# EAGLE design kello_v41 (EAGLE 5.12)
TP_SIGNAL_NAME: IC4SDO
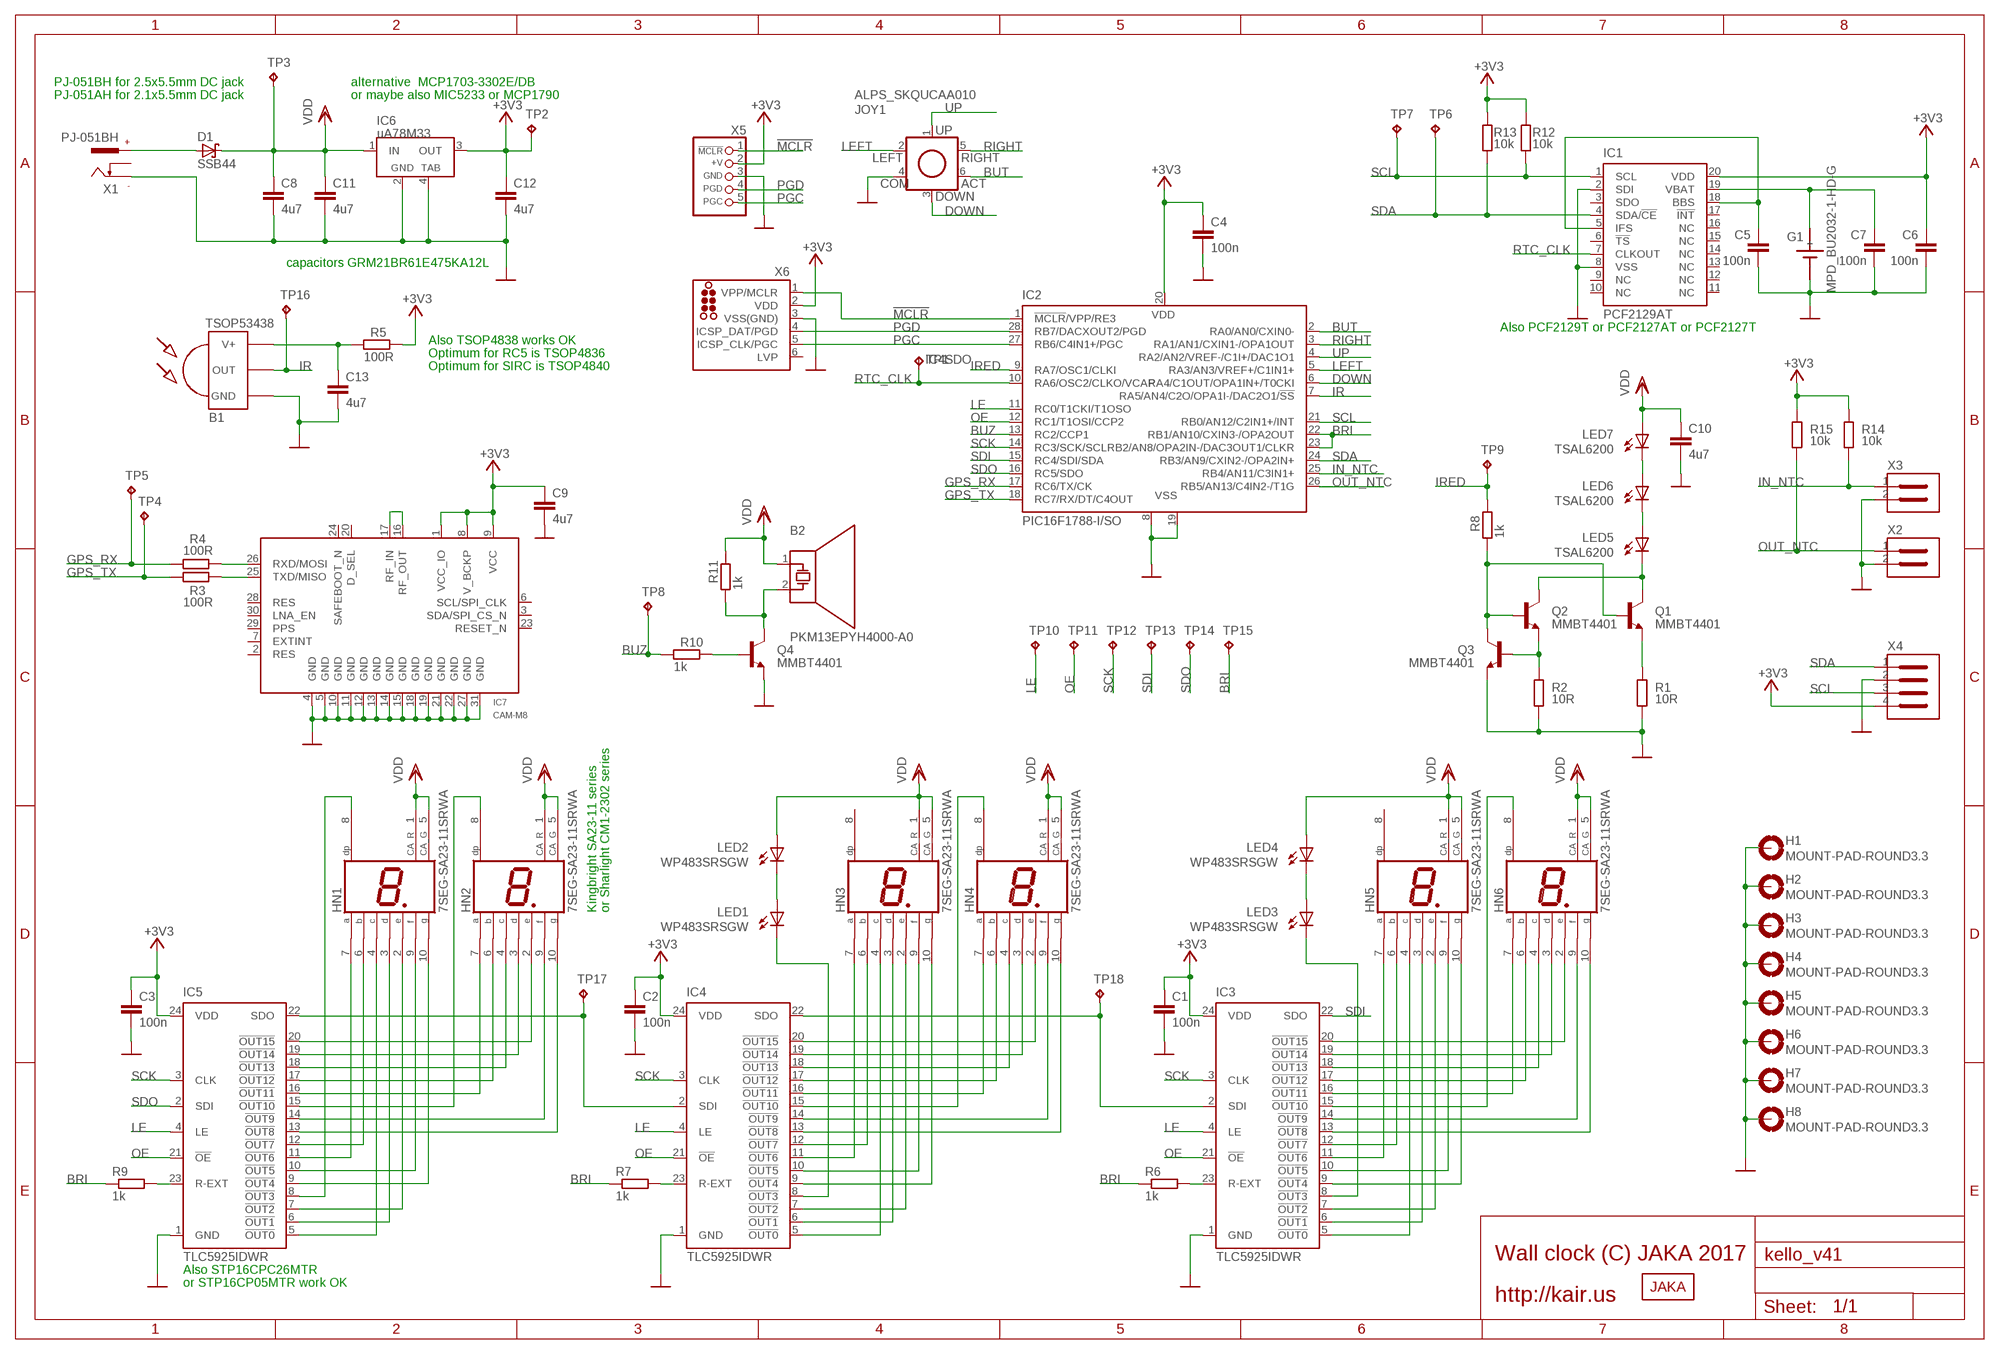
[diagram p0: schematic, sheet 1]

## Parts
B1  TSOP53438  TSOP4838VAAKA  [TSOP18XX_VAAKA]
B2  PKM13EPYH4000-A0  [PKM13]
C1  100n  C-EUC0805  [C0805]
C2  100n  C-EUC0805  [C0805]
C3  100n  C-EUC0805  [C0805]
C4  100n  C-EUC0805  [C0805]
C5  100n  C-EUC0805  [C0805]
C6  100n  C-EUC0805  [C0805]
C7  100n  C-EUC0805  [C0805]
C8  4u7  C-EUC0805  [C0805]
C9  4u7  C-EUC0805  [C0805]
C10  4u7  C-EUC0805  [C0805]
C11  4u7  C-EUC0805  [C0805]
C12  4u7  C-EUC0805  [C0805]
C13  4u7  C-EUC0805  [C0805]
D1  SSB44  SCHOTTKY-SSB44  [SMB]
G1  MPD_BU2032-1-HD-G  [MPD_BU2032-1-HD-G]
H1  MOUNT-PAD-ROUND3.3  [3,3-PAD]
H2  MOUNT-PAD-ROUND3.3  [3,3-PAD]
H3  MOUNT-PAD-ROUND3.3  [3,3-PAD]
H4  MOUNT-PAD-ROUND3.3  [3,3-PAD]
H5  MOUNT-PAD-ROUND3.3  [3,3-PAD]
H6  MOUNT-PAD-ROUND3.3  [3,3-PAD]
H7  MOUNT-PAD-ROUND3.3  [3,3-PAD]
H8  MOUNT-PAD-ROUND3.3  [3,3-PAD]
HN1  7SEG-SA23-11SRWA  [SA23-11]
HN2  7SEG-SA23-11SRWA  [SA23-11]
HN3  7SEG-SA23-11SRWA  [SA23-11]
HN4  7SEG-SA23-11SRWA  [SA23-11]
HN5  7SEG-SA23-11SRWA  [SA23-11]
HN6  7SEG-SA23-11SRWA  [SA23-11]
IC1  PCF2129AT  [SO20]
IC2  PIC16F1788-I/SO  [SO28W]
IC3  TLC5925IDWR  [SO24W]
IC4  TLC5925IDWR  [SO24W]
IC5  TLC5925IDWR  [SO24W]
IC6  uA78M33  VREG_3PIN_FIXED_TAB-SOT223  [SOT223]
IC7  CAM-M8  [UC530M]
JOY1  ALPS_SKQUCAA010  [ALPS_SKQUCAA010]
LED1  WP483SRSGW  LED5MM  [LED5MM]
LED2  WP483SRSGW  LED5MM  [LED5MM]
LED3  WP483SRSGW  LED5MM  [LED5MM]
LED4  WP483SRSGW  LED5MM  [LED5MM]
LED5  TSAL6200  LED5MM  [LED5MM]
LED6  TSAL6200  LED5MM  [LED5MM]
LED7  TSAL6200  LED5MM  [LED5MM]
Q1  MMBT4401  MMBT3904LT1-NPN-SOT-23-BEC  [SOT-23]
Q2  MMBT4401  MMBT3904LT1-NPN-SOT-23-BEC  [SOT-23]
Q3  MMBT4401  MMBT3904LT1-NPN-SOT-23-BEC  [SOT-23]
Q4  MMBT4401  MMBT3904LT1-NPN-SOT-23-BEC  [SOT-23]
R1  10R  R-EU_R0805  [R0805]
R2  10R  R-EU_R0805  [R0805]
R3  100R  R-EU_R0805  [R0805]
R4  100R  R-EU_R0805  [R0805]
R5  100R  R-EU_R0805  [R0805]
R6  1k  R-EU_R0805  [R0805]
R7  1k  R-EU_R0805  [R0805]
R8  1k  R-EU_R0805  [R0805]
R9  1k  R-EU_R0805  [R0805]
R10  1k  R-EU_R0805  [R0805]
R11  1k  R-EU_R0805  [R0805]
R12  10k  R-EU_R0805  [R0805]
R13  10k  R-EU_R0805  [R0805]
R14  10k  R-EU_R0805  [R0805]
R15  10k  R-EU_R0805  [R0805]
TP1  TESTPOINT  TESTPOINTTH_1MM  [P1-10]
TP2  TESTPOINT  TESTPOINTTH_1MM  [P1-10]
TP3  TESTPOINT  TESTPOINTTH_1MM  [P1-10]
TP4  TESTPOINT  TESTPOINTTH_1MM  [P1-10]
TP5  TESTPOINT  TESTPOINTTH_1MM  [P1-10]
TP6  TESTPOINT  TESTPOINTTH_1MM  [P1-10]
TP7  TESTPOINT  TESTPOINTTH_1MM  [P1-10]
TP8  TESTPOINT  TESTPOINTTH_1MM  [P1-10]
TP9  TESTPOINT  TESTPOINTTH_1MM  [P1-10]
TP10  TESTPOINT  TESTPOINTTH_1MM  [P1-10]
TP11  TESTPOINT  TESTPOINTTH_1MM  [P1-10]
TP12  TESTPOINT  TESTPOINTTH_1MM  [P1-10]
TP13  TESTPOINT  TESTPOINTTH_1MM  [P1-10]
TP14  TESTPOINT  TESTPOINTTH_1MM  [P1-10]
TP15  TESTPOINT  TESTPOINTTH_1MM  [P1-10]
TP16  TESTPOINT  TESTPOINTTH_1MM  [P1-10]
TP17  TESTPOINT  TESTPOINTTH_1MM  [P1-10]
TP18  TESTPOINT  TESTPOINTTH_1MM  [P1-10]
U$1  JAKA_LOGO_SMALL  [JAKA_LOGO_SMALL]
X1  PJ-051BH  [PJ-051BH]
X2  S2B-XH-A(LF)(SN)  [S2B-XH-A]
X3  S2B-XH-A(LF)(SN)  [S2B-XH-A]
X4  S4B-XH-A(LF)(SN)  [S4B-XH-A]
X5  CON_HEADER_PRG_PIC_ICSPB  [HEADER_PRG_1X05_ICSP_B]
X6  TC2030-MCP-NL-JKA  [TC2030-MCP-NL-JKA]

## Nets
!MCLR: IC2.1(!MCLR!/VPP/RE3) X5.1(/MCLR) X6.1(VPP/MCLR)
+3V3: C1.1 C2.1 C3.1 C4.1 C6.1 C9.1 C12.1 IC1.20(VDD) IC2.20(VDD) IC3.24(VDD) IC4.24(VDD) IC5.24(VDD) IC6.3(OUT) IC7.1(VCC_IO) IC7.8(V_BCKP) IC7.9(VCC) R5.1 R12.2 R13.2 R14.2 R15.2 TP2.TP X4.4 X5.2(+V) X6.2(VDD)
BRI: IC2.22(RB1/AN10/CXIN3-/OPA2OUT) IC2.23(RB2/AN8/OPA2IN-/DAC3OUT1/CLKR) R6.1 R7.1 R9.1 TP15.TP
BUT: IC2.2(RA0/AN0/CXIN0-) JOY1.6(ACT)
BUZ: IC2.13(RC2/CCP1) R10.2 TP8.TP
DOWN: IC2.6(RA4/C1OUT/OPA1IN+/T0CKI) JOY1.3(DOWN)
GND: B1.GND C1.2 C2.2 C3.2 C4.2 C5.2 C6.2 C7.2 C8.2 C9.2 C10.2 C11.2 C12.2 C13.2 G1.N(-) H1.B3,3(MOUNT) H2.B3,3(MOUNT) H3.B3,3(MOUNT) H4.B3,3(MOUNT) H5.B3,3(MOUNT) H6.B3,3(MOUNT) H7.B3,3(MOUNT) H8.B3,3(MOUNT) IC1.2(SDI) IC1.8(VSS) IC2.8(VSS) IC2.19(VSS) IC3.1(GND) IC4.1(GND) IC5.1(GND) IC6.2(GND) IC6.4(GND1) IC7.4(GND) IC7.5(GND) IC7.10(GND) IC7.11(GND) IC7.12(GND) IC7.13(GND) IC7.14(GND) IC7.15(GND) IC7.18(GND) IC7.19(GND) IC7.21(GND) IC7.22(GND) IC7.27(GND) IC7.31(GND) JOY1.4(COM) Q3.2(E) Q4.2(E) R1.1 R2.1 X1.BARREL(-) X2.2 X3.2 X4.2 X5.3(GND) X6.3(VSS(GND))
GPS_RX: IC2.17(RC6/TX/CK) R4.2 TP5.TP
GPS_TX: IC2.18(RC7/RX/DT/C4OUT) R3.2 TP4.TP
IN_NTC: IC2.25(RB4/AN11/C3IN1+) R14.1 X3.1
IR: B1.OUT IC2.7(RA5/AN4/C2O/OPA1I-/DAC2O1/!SS) TP16.TP
IRED: IC2.9(RA7/OSC1/CLKI) R8.1 TP9.TP
LE: IC2.11(RC0/T1CKI/T1OSO) IC3.4(LE) IC4.4(LE) IC5.4(LE) TP10.TP
LEFT: IC2.5(RA3/AN3/VREF+/C1IN1+) JOY1.2(LEFT)
N$1: IC7.16(RF_OUT) IC7.17(RF_IN)
N$2: IC5.23(R-EXT) R9.2
N$3: HN1.7(A) IC5.11(!OUT6)
N$4: HN1.6(B) IC5.12(!OUT7)
N$5: HN1.4(C) IC5.5(!OUT0)
N$6: HN1.3(D) IC5.6(!OUT1)
N$7: HN1.2(E) IC5.7(!OUT2)
N$8: HN1.9(F) IC5.10(!OUT5)
N$9: HN1.10(G) IC5.9(!OUT4)
N$10: B1.VCC(V+) C13.1 R5.2
N$11: HN2.7(A) IC5.16(!OUT11)
N$12: HN2.6(B) IC5.17(!OUT12)
N$13: HN2.4(C) IC5.18(!OUT13)
N$14: HN2.3(D) IC5.19(!OUT14)
N$15: HN2.2(E) IC5.20(!OUT15)
N$16: HN2.9(F) IC5.14(!OUT9)
N$17: HN2.10(G) IC5.13(!OUT8)
N$18: HN2.8(DP) IC5.15(!OUT10)
N$19: HN3.7(A) IC4.11(!OUT6)
N$20: HN3.6(B) IC4.12(!OUT7)
N$21: HN3.4(C) IC4.5(!OUT0)
N$22: HN3.3(D) IC4.6(!OUT1)
N$23: HN3.2(E) IC4.7(!OUT2)
N$24: HN3.9(F) IC4.10(!OUT5)
N$25: HN3.10(G) IC4.9(!OUT4)
N$26: IC4.8(!OUT3) LED1.K(C)
N$27: HN4.7(A) IC4.16(!OUT11)
N$28: HN4.6(B) IC4.17(!OUT12)
N$29: HN4.4(C) IC4.18(!OUT13)
N$30: HN4.3(D) IC4.19(!OUT14)
N$31: HN4.2(E) IC4.20(!OUT15)
N$32: HN4.9(F) IC4.14(!OUT9)
N$33: HN4.10(G) IC4.13(!OUT8)
N$34: HN4.8(DP) IC4.15(!OUT10)
N$35: HN5.7(A) IC3.11(!OUT6)
N$36: HN5.6(B) IC3.12(!OUT7)
N$37: HN5.4(C) IC3.5(!OUT0)
N$38: HN5.3(D) IC3.6(!OUT1)
N$39: HN5.2(E) IC3.7(!OUT2)
N$40: HN5.9(F) IC3.10(!OUT5)
N$41: HN5.10(G) IC3.9(!OUT4)
N$42: LED3.A LED4.K(C)
N$43: HN6.7(A) IC3.16(!OUT11)
N$44: HN6.6(B) IC3.17(!OUT12)
N$45: HN6.4(C) IC3.18(!OUT13)
N$46: HN6.3(D) IC3.19(!OUT14)
N$47: HN6.2(E) IC3.20(!OUT15)
N$48: HN6.9(F) IC3.14(!OUT9)
N$49: HN6.10(G) IC3.13(!OUT8)
N$50: HN6.8(DP) IC3.15(!OUT10)
N$51: IC4.23(R-EXT) R7.2
N$52: LED1.A LED2.K(C)
N$53: IC3.8(!OUT3) LED3.K(C)
N$54: IC3.23(R-EXT) R6.2
N$55: IC4.2(SDI) IC5.22(SDO) TP17.TP
N$56: IC3.2(SDI) IC4.22(SDO) TP18.TP
N$57: Q2.2(E) Q3.1(B) R2.2
N$58: Q1.2(E) R1.2
N$59: Q1.1(B) Q2.1(B) Q3.3(C) R8.2
N$60: Q4.1(B) R10.1
N$61: B2.2 Q4.3(C) R11.2
N$62: LED6.A LED7.K(C)
N$63: C7.1 G1.P(+) IC1.19(VBAT)
N$64: LED5.K(C) Q1.3(C) Q2.3(C)
N$65: LED5.A LED6.K(C)
N$66: IC7.26(RXD/MOSI) R4.1
N$67: IC7.25(TXD/MISO) R3.1
N$68: HN1.8(DP) IC5.8(!OUT3)
N$69: C5.1 IC1.5(IFS) IC1.18(BBS)
N$90: D1.A X1.CENTER(+)
OE: IC2.12(RC1/T1OSI/CCP2) IC3.21(!OE) IC4.21(!OE) IC5.21(!OE) TP11.TP
OUT_NTC: IC2.26(RB5/AN13/C4IN2-/T1G) R15.1 X2.1
PGC: IC2.27(RB6/C4IN1+/PGC) X5.5(PGC) X6.5(ICSP_CLK/PGC)
PGD: IC2.28(RB7/DACXOUT2/PGD) X5.4(PGD) X6.4(ICSP_DAT/PGD)
RIGHT: IC2.3(RA1/AN1/CXIN1-/OPA1OUT) JOY1.5(RIGHT)
RTC_CLK: IC1.7(CLKOUT) IC2.10(RA6/OSC2/CLKO/VCAP) TP1.TP
SCK: IC2.14(RC3/SCK/SCL) IC3.3(CLK) IC4.3(CLK) IC5.3(CLK) TP12.TP
SCL: IC1.1(SCL) IC2.21(RB0/AN12/C2IN1+/INT) R12.1 TP7.TP X4.3
SDA: IC1.4(SDA/!CE) IC2.24(RB3/AN9/CXIN2-/OPA2IN+) R13.1 TP6.TP X4.1
SDI: IC2.15(RC4/SDI/SDA) IC3.22(SDO) TP13.TP
SDO: IC2.16(RC5/SDO) IC5.2(SDI) TP14.TP
UP: IC2.4(RA2/AN2/VREF-/C1I+/DAC1O1) JOY1.1(UP)
VDD: B2.1 C8.1 C10.1 C11.1 D1.C HN1.1(CA_R) HN1.5(CA_G) HN2.1(CA_R) HN2.5(CA_G) HN3.1(CA_R) HN3.5(CA_G) HN4.1(CA_R) HN4.5(CA_G) HN5.1(CA_R) HN5.5(CA_G) HN6.1(CA_R) HN6.5(CA_G) IC6.1(IN) LED2.A LED4.A LED7.A R11.1 TP3.TP
Unconnected: HN3.8(DP) HN5.8(DP) IC1.3(SDO) IC1.6(!TS) IC1.9(NC) IC1.10(NC) IC1.11(NC) IC1.12(NC) IC1.13(NC) IC1.14(NC) IC1.15(NC) IC1.16(NC) IC1.17(!INT) IC7.2(RES) IC7.3(SDA/SPI_CS_N) IC7.6(SCL/SPI_CLK) IC7.7(EXTINT) IC7.20(D_SEL) IC7.23(RESET_N) IC7.24(SAFEBOOT_N) IC7.28(RES) IC7.29(PPS) IC7.30(LNA_EN) X1.K X6.6(LVP)

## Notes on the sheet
- PJ-051BH for 2.5x5.5mm DC jack | alternative  MCP1703-3302E/DB
- PJ-051AH for 2.1x5.5mm DC jack | or maybe also MIC5233 or MCP1790
- capacitors GRM21BR61E475KA12L
- Also PCF2129T or PCF2127AT or PCF2127T
- Also TSOP4838 works OK
- Optimum for RC5 is TSOP4836
- Optimum for SIRC is TSOP4840
- Kingbright SA23-11 series | or Sharlight CM1-2302 series
- Wall clock (C) JAKA 2017
- Also STP16CPC26MTR
- or STP16CP05MTR work OK
- http://kair.us

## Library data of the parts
B1 = omat:TSOP4838: IR Receiver and Demodulator
B2 = omat:PKM13EPYH4000-A0
C1-C13 = dual_atari:C-EU: CAPACITOR, European symbol
D1 = omat:SCHOTTKY-
G1 = omat:MPD_BU2032-1-HD-G
H1-H8 = omat:MOUNT-PAD-ROUND: MOUNTING PAD, round
HN1-HN6 = omat:7SEG-: Various 2.3" 7-segment displays
IC1 = omat:PCF2129AT
IC2 = omat:PIC16F1788
IC3-IC5 = omat:TLC5925
IC6 = omat:VREG_3PIN_FIXED_TAB
IC7 = omat:CAM-M8
JOY1 = omat:ALPS_SKQUCAA010
LED1-LED7 = kello:LED: LED
Q1-Q4 = omat:*-NPN-: NPN Transistror
R1-R15 = omat:R-EU_: RESISTOR, European symbol
TP1-TP18 = omat:TESTPOINT
U$1 = omat:JAKA_LOGO
X1 = kello:PJ-051BH
X2 X3 = omat:S2B-XH-A(LF)(SN)
X4 = omat:S4B-XH-A(LF)(SN)
X5 = omat:CON_HEADER_PRG_PIC_ICSP: 5-pin PIC In Circuit Serial Programming header
X6 = dual_atari:TC2030: TAG-CONNECT ISP Connector Manufacturer: Tag-Connect Cable for easy In-Circuit PCB Programming. Designed for Microchip ICD2, suitable for many others. Two variants - one "with legs" (for hads-free fit on PCB) and another "without legs" for quick programming. PADDescription 1MCLR/Vpp 2Vdd 3GND 4PGD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

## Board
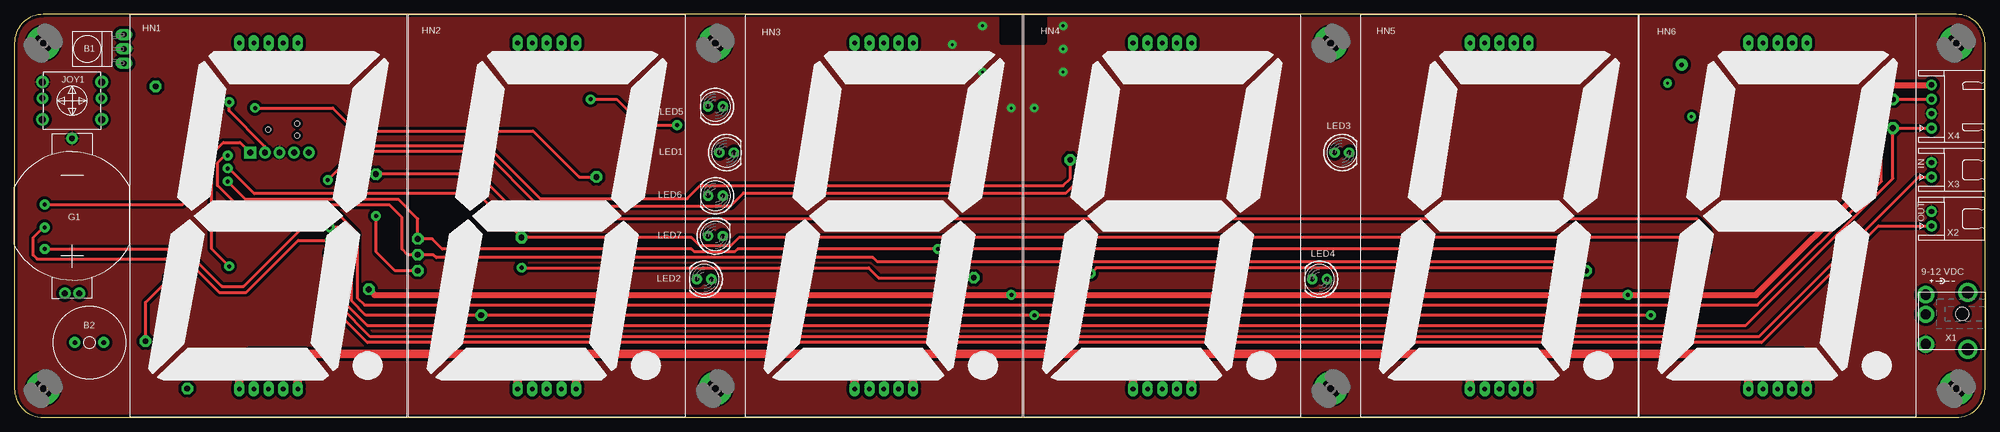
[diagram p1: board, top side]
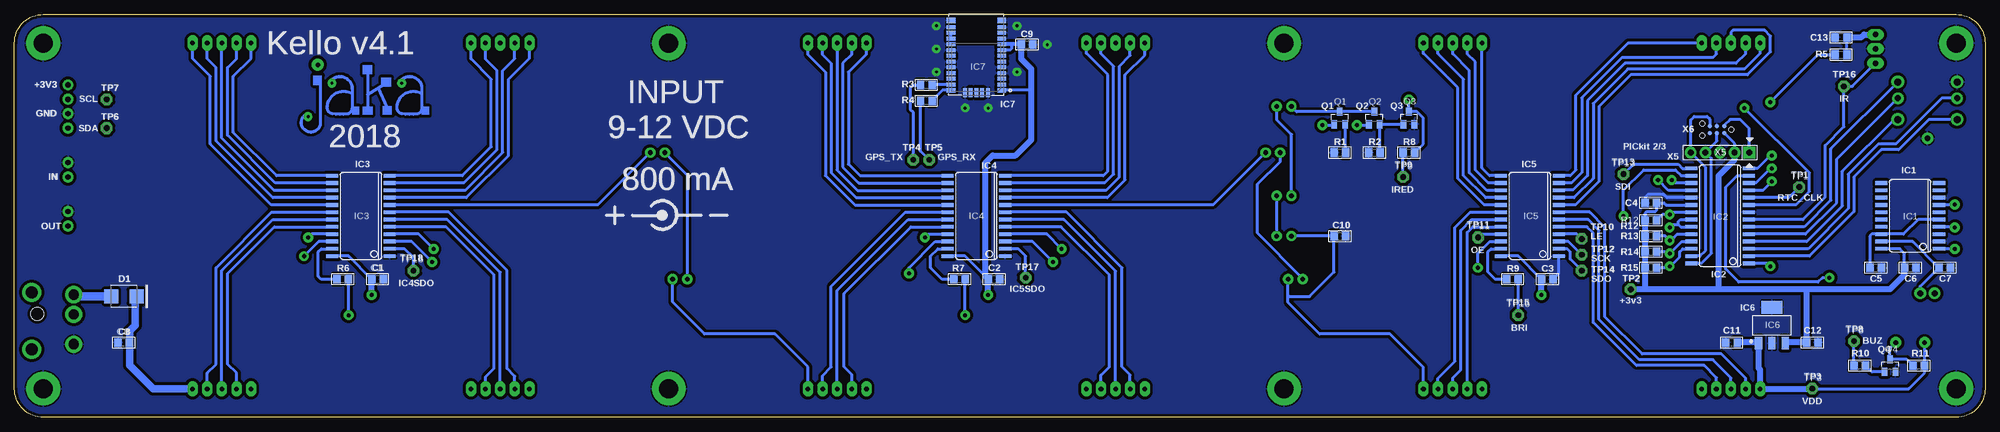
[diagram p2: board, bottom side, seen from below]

Size 342 x 70 mm. Coordinates in mm from the lower left corner, seen from the top.
Outline: 342,65 arc90 337,70 5,70 arc90 0,65 0,5 arc90 5,0 337,0 arc90 342,5 342,65
Copper layers (1*16): Top 0.035mm / dielectric 1.5mm / Bottom 0.035mm
Design rules "default *": minimum track width 0.3mm, minimum drill 0.7mm, track to track 0.5mm, track to pad 0.5mm, pad to pad 0.5mm, via to via 0.5mm, smd to smd 0.3mm, copper to edge 0.5mm, drill to drill 0.3mm, minimum pad ring 0.5mm, minimum via ring 0.5mm, stop-mask expansion 4mil, vias tented up to drill 0mil, thermal gap 10mil
bRestrict: area 170.8,59.5 to 170.8,69; area 179.5,61 to 179.5,69; area 176.5,56.4 to 176.6,56.4

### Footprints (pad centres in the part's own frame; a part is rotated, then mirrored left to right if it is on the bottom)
TSOP18XX_VAAKA = drill 1 long: GND -0.001,-0.027; OUT -2.501,-0.027; VCC 2.499,-0.027
PKM13 = drill 0.8 pad 1.9 round: 1 -2.5,0; 2 2.5,0
C0805 = smd 1.3 x 1.5: 1 -1,0; 2 1,0
SMB = smd 2.4 x 2.4: A 2.2,0; C -2.2,0
MPD_BU2032-1-HD-G = drill 1 pad 2 round: N 0,-13.45; P -1.25,13.45; P2 1.25,13.45
3,3-PAD = drill 3.3 pad 5.842 round: B3,3 0,0
SA23-11 = drill 0.8 long: 1 -5.08,-30.05; 2 -2.54,-30.05; 3 0,-30.05; 4 2.54,-30.05; 5 5.08,-30.05; 6 5.08,30.05; 7 2.54,30.05; 8 0,30.05; 9 -2.54,30.05; 10 -5.08,30.05
SO20 = smd 0.65 x 2.1: 1 -5.715,-5; 2 -4.445,-5; 3 -3.175,-5; 4 -1.905,-5; 5 -0.635,-5; 6 0.635,-5; 7 1.905,-5; 8 3.175,-5; 9 4.445,-5; 10 5.715,-5; 11 5.715,5; 12 4.445,5; 13 3.175,5; 14 1.905,5; 15 0.635,5; 16 -0.635,5; 17 -1.905,5; 18 -3.175,5; 19 -4.445,5; 20 -5.715,5
SO28W = smd 0.65 x 2.1: 1 -8.255,-5; 2 -6.985,-5; 3 -5.715,-5; 4 -4.445,-5; 5 -3.175,-5; 6 -1.905,-5; 7 -0.635,-5; 8 0.635,-5; 9 1.905,-5; 10 3.175,-5; 11 4.445,-5; 12 5.715,-5; 13 6.985,-5; 14 8.255,-5; 15 8.255,5; 16 6.985,5; 17 5.715,5; 18 4.445,5; 19 3.175,5; 20 1.905,5; 21 0.635,5; 22 -0.635,5; 23 -1.905,5; 24 -3.175,5; 25 -4.445,5; 26 -5.715,5; 27 -6.985,5; 28 -8.255,5
SO24W = smd 0.65 x 2.1: 1 -6.985,-5; 2 -5.715,-5; 3 -4.445,-5; 4 -3.175,-5; 5 -1.905,-5; 6 -0.635,-5; 7 0.635,-5; 8 1.905,-5; 9 3.175,-5; 10 4.445,-5; 11 5.715,-5; 12 6.985,-5; 13 6.985,5; 14 5.715,5; 15 4.445,5; 16 3.175,5; 17 1.905,5; 18 0.635,5; 19 -0.635,5; 20 -1.905,5; 21 -3.175,5; 22 -4.445,5; 23 -5.715,5; 24 -6.985,5
SOT223 = smd 1.219 x 2.235: 1 -2.311,-3.099; 2 0,-3.099; 3 2.311,-3.099 | smd 3.6 x 2.2: 4 0,3.099
UC530M = smd 1.5 x 0.7: 1 -4.4,6.2; 2 -4.4,5.2; 3 -4.4,4.2; 4 -4.4,3.2; 5 -4.4,2.2; 6 -4.4,1.2; 7 -4.4,0.2; 8 -4.4,-0.8; 9 -4.4,-1.8; 10 -4.4,-2.8; 11 -4.4,-3.8; 12 -4.4,-4.8; 15 4.4,-4.8; 16 4.4,-3.8; 17 4.4,-2.8; 18 4.4,-1.8; 19 4.4,-0.8; 20 4.4,0.2; 21 4.4,1.2; 22 4.4,2.2; 23 4.4,3.2; 24 4.4,4.2; 25 4.4,5.2; 26 4.4,6.2 | smd 1.5 x 1: 13 -4.4,-5.95; 14 4.4,-5.95 | smd 0.7 x 1.5: 27 2,6.6; 28 1,6.6; 29 0,6.6; 30 -1,6.6; 31 -2,6.6
ALPS_SKQUCAA010 = drill 1.2 round: 1 -5.15,3.25; 3 -5.15,-3.25; 4 5.15,-3.25; 6 5.15,3.25 | drill 1 round: 2 -5.15,-0.45; 5 5.15,-0.45
LED5MM = drill 0.8 round: A -1.27,0; K 1.27,0
SOT-23 = smd 1 x 1.4: 1 -0.95,-1.1; 2 0.95,-1.1; 3 0,1.1
R0805 = smd 1.3 x 1.5: 1 -1,0; 2 1,0
P1-10 = drill 1 pad 1.9 octagon: TP 0,0
JAKA_LOGO_SMALL = drill 0.8 pad 2.1 round: B5,1 -8.1,5.5 | drill 0.5 pad 1.5 round: B5,2 -9.8,-3.5; B5,3 -5.65,2.3; B5,4 6.45,2.3
PJ-051BH = drill 1.8 pad 3 round: BARREL 6.3,5.3; CENTER 6.3,-3.3; K 6.3,0.1 | drill 2.1 pad 3.3 round: SHIELD1 -1,-3.7; SHIELD2 -1,6.2 | hole 2.3: 0,0
S2B-XH-A = drill 0.9 pad 1.9 round: 1 -1.25,0; 2 1.25,0
S4B-XH-A = drill 0.9 pad 1.9 round: 1 -3.75,0; 2 -1.25,0; 3 1.25,0; 4 3.75,0
HEADER_PRG_1X05_ICSP_B = drill 1 square: 1 -5.08,0 | drill 1 round: 2 -2.54,0; 3 0,0; 4 2.54,0; 5 5.08,0
TC2030-MCP-NL-JKA = smd 0.787 x 0.787: 1 1.27,-0.635; 2 1.27,0.635; 3 2.54,-0.635; 4 2.54,0.635; 5 3.81,-0.635; 6 3.81,0.635 | hole 0.9: 0,0; 5.08,-1.016; 5.08,1.016

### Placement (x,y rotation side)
B1  19,64 90 top
B2  13,13 0 top
C1  279,24 0 bottom
C2  172,24 0 bottom
C3  76,24 0 bottom
C4  58,37.25 180 bottom
C5  19,26 0 bottom
C6  13,26 0 bottom
C7  7,26 0 bottom
C8  323,13 180 bottom
C9  166.25,64.75 0 bottom
C10  112,31.5 0 bottom
C11  44,13 180 bottom
C12  30,13 0 bottom
C13  25,66 180 bottom
D1  323,21 180 bottom
DRILEGEND  [DRILEGEND]  not placed on the board
G1  10,35 180 top
H1  5,5 0 top
H2  5,65 0 top
H3  337,5 0 top
H4  337,65 0 top
H5  121.65,65 0 top
H6  228.45,65 0 top
H7  121.65,5 0 top
H8  228.45,5 0 top
HN1  44.1,35 0 top
HN2  92.4,35 0 top
HN3  150.9,35 0 top
HN4  199.2,35 0 top
HN5  257.7,35 0 top
HN6  306,35 0 top
IC1  13,35 90 bottom
IC2  46,35 90 bottom
IC3  281.85,35 90 bottom
IC4  175.05,35 90 bottom
IC5  79,35 90 bottom
IC6  37,16 0 bottom
IC7  175.05,63 180 bottom
JOY1  10,55 180 top
LED1  123.6,46 0 top
LED2  119.7,24 180 top
LED3  230.4,46 0 top
LED4  226.5,24 180 top
LED5  121.65,54 180 top
LED6  121.65,38.5 180 top
LED7  121.65,31.5 0 top
Q1  112,52 0 bottom
Q2  106,52 0 bottom
Q3  100,52 0 bottom
Q4  16.5,9 0 bottom
R1  112,46 0 bottom
R2  106,46 0 bottom
R3  183.75,57.75 180 bottom
R4  183.75,55 180 bottom
R5  25,63 0 bottom
R6  285,24 180 bottom
R7  178,24 180 bottom
R8  100,46 0 bottom
R9  82,24 180 bottom
R10  21.75,9 180 bottom
R11  11.5,9 180 bottom
R12  58,34.25 180 bottom
R13  58,31.5 180 bottom
R14  58,28.75 180 bottom
R15  58,26 180 bottom
TP1  32.25,40 0 bottom
TP2  61.5,22.25 0 bottom
TP3  30,5 0 bottom
TP4  186,44.75 0 bottom
TP5  183.25,44.75 0 bottom
TP6  326,50.25 0 bottom
TP7  326,55.25 0 bottom
TP8  22.75,13.25 0 bottom
TP9  101,41.75 0 bottom
TP10  70,31 0 bottom
TP11  88,31.25 0 bottom
TP12  70,28.25 0 bottom
TP13  62.75,42.25 0 bottom
TP14  70,25.5 0 bottom
TP15  81,17.75 0 bottom
TP16  24.5,57.5 0 bottom
TP17  166.5,24.25 0 bottom
TP18  272.75,25.5 0 bottom
U$1  281.25,55.75 0 bottom
X1  338,18 180 top
X2  332.7,34.5 90 top
X3  332.7,43 90 top
X4  332.7,54 90 top
X5  46,46 180 bottom
X6  44,50 180 bottom

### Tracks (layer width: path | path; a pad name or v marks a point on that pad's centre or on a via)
!MCLR  (via drill 0.7)
  Top 0.5: v37.25,26.25 34.25,29.25 34.25,45.75 36.25,47.75 39.17,47.75 X5.1
  Bottom 0.5: X5.1 40.92,50.17 42.5,51.75 44.25,51.75 45.27,50.73 X6.1 | IC2.1 37.74,26.75 v37.25,26.25
+3V3  (via drill 0.7)
  Top 0.5: X5.2 43.46,47.04 37.25,53.25 v37.25,54.75
  Top 1: TP2.TP 62.5,21.25 v77,21.25 v173,21.25 v280,21.25 302.25,21.25 322.25,41.25 322.25,56.25 323.75,57.75 X4.4
  Bottom 0.5: X5.2 43.46,47.55 X6.2 | C2.1 173.38,24.38 177.01,28.02 IC4.24 | C3.1 81.02,28.02 IC5.24 | R5.1 29,63 v37.25,54.75 | IC2.20 55.41,36.91 55.75,37.25 C4.1 57,36 57.25,35.75 58.75,35.75 59,35.5 R12.2 | C1.1 284.01,28.02 IC3.24 | IC7.8 169.2,63.8 169,64 169,64.8 | C6.1 14,28.5 14.79,29.29 IC1.20 | IC7.1 165.5,56.8 165.5,57
  Bottom 0.7: IC7.9 169,64.8 167.3,64.8 C9.1
  Bottom 1: IC6.3 34.59,13 C12.1 31,22.25 | 46.25,22.25 46.25,42 43.46,44.79 X5.2 | 46.25,22.25 59,22.25 | 59,22.25 R15.2 R14.2 R13.2 R12.2 | 31,22.25 46.25,22.25 | 59,22.25 TP2.TP | v280,21.25 C1.1 | v173,21.25 C2.1 | v77,21.25 C3.1 | 173.38,24.38 173.5,24.5 173.5,44.25 172.25,45.5 168.25,45.5 165.5,48.25 165.5,57 165.5,60.5 167.25,62.25 C9.1 | 31,22.25 16.5,22.25 14,24.75 C6.1
BRI  (via drill 0.7)
  Top 0.5: v284,17.75 v177,17.75 TP15.TP 61,17.75 58.5,20.25 58.5,30.75 56.25,33 v54.75,33
  Bottom 0.5: TP15.TP R9.1 | IC2.23 52.84,33.09 53.25,33.5 | 53.25,33.5 53.25,34 52.88,34.37 IC2.22 | 53.25,33.5 54.25,33.5 v54.75,33 | v177,17.75 R7.1 | v284,17.75 R6.1
BUT
  Bottom 0.5: JOY1.6 9.75,51.75 15,46.5 18,46.5 22.75,41.75 22.75,35.75 30.48,28.02 IC2.2
BUZ  (via drill 0.7)
  Top 0.5: TP8.TP 22.75,20 v27,24.25
  Bottom 0.5: IC2.13 43.02,41.98 45,40 45,25.75 42.75,23.5 29,23.5 28.25,24.25 v27,24.25 | R10.2 TP8.TP
DOWN
  Bottom 0.5: JOY1.3 26.75,46.65 26.75,37.75 31.41,33.09 IC2.6
GND  (via drill 0.5)
  Bottom 0.5: IC5.1 74,25 C3.2 | C4.2 59,38.25 58.5,38.75 55.75,38.75 55.17,38.17 IC2.19
  other vias: 168,68 162.75,64.75 168,60 182,68 182,64 182,60 177,53.75 173,53.75
  pour Bottom (isolate 0.5): 5,0 arc-90 0,5 0,65 arc-90 5,70 337,70 arc-90 342,65 342,5 arc-90 337,0
  pour Top (isolate 0.5): 5,0 arc-90 0,5 0,65 arc-90 5,70 337,70 arc-90 342,65 342,5 arc-90 337,0
GPS_RX  (via drill 0.7)
  Top 0.5: v54.4,41.25 60.4,47.25 82,47.25 91.25,38 116.75,38 119,40.25 182,40.25 183.25,41.5 TP5.TP
  Bottom 0.5: IC2.17 53.87,40.72 v54.4,41.25 | R4.2 184.75,46.25 TP5.TP
GPS_TX  (via drill 0.7)
  Top 0.5: v56.75,41.25 61.75,46.25 81.5,46.25 91,36.75 124.25,36.75 126.5,39 182.5,39 186,42.5 TP4.TP
  Bottom 0.5: IC2.18 54.95,39.45 v56.75,41.25 | TP4.TP 186,53 186.5,53.5 186.5,57.25 186,57.75 R3.2
IN_NTC  (via drill 0.7)
  Top 0.5: X3.1 330.5,41.75 302.75,14 61.75,14 56.5,19.25 56.5,28.25 56.25,28.5 v54.75,28.5
  Bottom 0.5: R14.1 55,28.75 v54.75,28.5 54.7,28.5 52.65,30.55 IC2.25
IR
  Bottom 0.5: B1.OUT 23.02,57.5 TP16.TP 24.5,50.5 27.75,47.25 27.75,38.25 31.64,34.37 IC2.7
IRED  (via drill 0.7)
  Top 0.5: v41.75,53.75 55.25,53.75 59.25,49.75 90,49.75 98,41.75 TP9.TP
  Bottom 0.5: IC2.9 32.84,36.91 30.5,39.25 30.5,42.5 v41.75,53.75 | TP9.TP R8.1
LE  (via drill 0.7)
  Top 0.5: v37,41 40.15,37.85 66.65,37.85 70,34.5 TP10.TP 72.5,31 74.25,29.25 117.5,29.25 118,28.75 125,28.75 125.5,29.25 v160.25,29.25 v269.25,29.25
  Bottom 0.5: TP10.TP 70.83,31.82 IC5.4 | IC2.11 38.55,39.45 v37,41 | IC3.4 271.82,31.82 v269.25,29.25 | v160.25,29.25 162.82,31.82 IC4.4
LEFT
  Bottom 0.5: JOY1.2 25.75,44.85 25.75,37.25 31.18,31.82 IC2.5
N$1
  Bottom 0.5: IC7.17 IC7.16
N$2
  Bottom 0.5: R9.2 85,24 86.25,25.25 86.25,28.75 85.72,29.29 IC5.23
N$3
  Bottom 0.5: IC5.11 71.78,40.72 70,42.5 70,55.5 63,62.5 47.25,62.5 46.64,63.11 HN1.7
N$4
  Bottom 0.5: IC5.12 72.02,41.98 71,43 71,56 61.95,65.05 HN1.6
N$5
  Bottom 0.5: IC5.5 69.09,33.09 68,32 68,16.5 60.5,9 48.75,9 46.64,6.89 HN1.4
N$6
  Bottom 0.5: IC5.6 68.86,34.37 67,32.5 67,17 60,10 47.25,10 44.1,6.85 HN1.3
N$7
  Bottom 0.5: IC5.7 68.64,35.63 66,33 66,17.5 59.5,11 45.75,11 41.56,6.81 HN1.2
N$8
  Bottom 0.5: IC5.10 74,39.5 71.5,39.5 69,42 69,55 62.5,61.5 43.25,61.5 41.56,63.19 HN1.9
N$9
  Bottom 0.5: IC5.9 71.33,38.17 68,41.5 68,54.5 62,60.5 41.75,60.5 39.02,63.23 HN1.10
N$10
  Bottom 0.5: R5.2 C13.1
  Bottom 1: B1.VCC 21,66.5 21.5,66 C13.1
N$11
  Bottom 0.5: IC5.16 86.67,38.17 90.5,42 90.5,58.75 94.94,63.19 HN2.7
N$12
  Bottom 0.5: IC5.17 86.91,36.91 91.5,41.5 91.5,57.25 97.48,63.23 HN2.6
N$13
  Bottom 0.5: IC5.18 89.36,35.63 92,33 92,9.75 94.94,6.81 HN2.4
N$14
  Bottom 0.5: IC5.19 89.14,34.37 91,32.5 91,8.25 92.4,6.85 HN2.3
N$15
  Bottom 0.5: IC5.20 88.91,33.09 89.86,32.14 HN2.2
N$16
  Bottom 0.5: IC5.14 86.22,40.72 88.5,43 88.5,61.75 89.86,63.11 HN2.9
N$17
  Bottom 0.5: IC5.13 85.98,41.98 87.32,43.32 HN2.10
N$18
  Bottom 0.5: IC5.15 86.44,39.45 89.5,42.5 89.5,60.25 92.4,63.15 HN2.8
N$19
  Bottom 0.5: IC4.11 152.78,40.72 151.25,42.25 151.25,61 153.44,63.19 HN3.7
N$20
  Bottom 0.5: IC4.12 153.01,41.98 152.25,42.75 152.25,59.5 155.98,63.23 HN3.6
N$21
  Bottom 0.5: IC4.5 160.34,33.09 152,24.75 152,8.75 153.44,7.31 HN3.4
N$22
  Bottom 0.5: IC4.6 159.87,34.37 150.9,25.4 HN3.3
N$23
  Bottom 0.5: IC4.7 159.38,35.63 149.75,26 149.75,8.75 148.36,7.36 HN3.2
N$24
  Bottom 0.5: IC4.10 152.56,39.45 150.25,41.75 150.25,61 148.36,62.89 HN3.9
N$25
  Bottom 0.5: IC4.9 152.32,38.17 149.25,41.25 149.25,59.5 145.82,62.93 HN3.10
N$26
  Bottom 0.5: LED1.K 133.97,36.91 IC4.8
N$27
  Bottom 0.5: IC4.16 195.93,38.17 200.25,42.5 200.25,61.5 201.74,62.99 HN4.7
N$28
  Bottom 0.5: IC4.17 196.16,36.91 201.25,42 201.25,60 204.28,63.03 HN4.6
N$29
  Bottom 0.5: IC4.18 187.37,35.63 200.25,22.75 200.25,8.75 201.74,7.26 HN4.4
N$30
  Bottom 0.5: IC4.19 186.88,34.37 199.2,22.05 HN4.3
N$31
  Bottom 0.5: IC4.20 186.41,33.09 198,21.5 198,8.75 196.66,7.41 HN4.2
N$32
  Bottom 0.5: IC4.14 195.47,40.72 198.25,43.5 198.25,61.5 196.66,63.09 HN4.9
N$33
  Bottom 0.5: IC4.13 195.24,41.98 197.25,44 197.25,60 194.12,63.13 HN4.10
N$34
  Bottom 0.5: IC4.15 195.69,39.45 199.25,43 199.25,65 HN4.8
N$35
  Bottom 0.5: IC3.11 264.04,40.72 258.25,46.5 258.25,60.25 260.24,62.24 HN5.7
N$36
  Bottom 0.5: IC3.12 264.26,41.98 259.25,47 259.25,58.75 262.78,62.28 HN5.6
N$37
  Bottom 0.5: IC3.5 267.1,33.09 258.75,24.75 258.75,8.5 260.24,7.01 HN5.4
N$38
  Bottom 0.5: IC3.6 266.87,34.37 257.7,25.2 HN5.3
N$39
  Bottom 0.5: IC3.7 266.63,35.63 256.5,25.5 256.5,8.5 255.16,7.16 HN5.2
N$40
  Bottom 0.5: IC3.10 263.81,39.45 257.25,46 257.25,60.25 255.16,62.34 HN5.9
N$41
  Bottom 0.5: IC3.9 263.57,38.17 256.25,45.5 256.25,58.75 252.62,62.38 HN5.10
N$42
  Bottom 0.5: LED4.K 225.23,42.1 LED3.A
N$43
  Bottom 0.5: IC3.16 297.18,38.17 307,48 307,60.75 308.54,62.29 HN6.7
N$44
  Bottom 0.5: IC3.17 297.4,36.91 308,47.5 308,59.25 311.08,62.33 HN6.6
N$45
  Bottom 0.5: IC3.18 297.37,35.63 307,26 307,9.25 308.54,7.71 HN6.4
N$46
  Bottom 0.5: IC3.19 297.13,34.37 306,25.5 HN6.3
N$47
  Bottom 0.5: IC3.20 296.9,33.09 305,25 305,9.25 303.46,7.71 HN6.2
N$48
  Bottom 0.5: IC3.14 296.71,40.72 305,49 305,60.75 303.46,62.29 HN6.9
N$49
  Bottom 0.5: IC3.13 296.49,41.98 304,49.5 304,59.25 300.92,62.33 HN6.10
N$50
  Bottom 0.5: IC3.15 296.94,39.45 306,48.5 HN6.8
N$51
  Bottom 0.5: R7.2 181,24 183,26 183,28 181.72,29.29 IC4.23
N$52
  Bottom 0.5: LED1.A 122.33,44.42 126.25,40.5 126.25,32 118.43,24.18 LED2.K
N$53
  Bottom 0.5: LED3.K 240.76,36.91 IC3.8
N$54
  Bottom 0.5: R6.2 288.75,24 289.25,24.5 289.25,28.75 288.71,29.29 IC3.23
N$55  (via drill 0.7)
  Top 0.5: TP17.TP 150,24.25 148.25,26 v88,26
  Bottom 0.5: IC4.2 167.78,29.29 166.5,28 TP17.TP | v88,26 88,28.5 85.94,30.55 IC5.22
N$56  (via drill 0.7)
  Top 0.5: v186.75,25 187.75,26 267.5,26 268.25,25.25 270.25,25.25 270.5,25.5 TP18.TP
  Bottom 0.5: IC3.2 274.29,29.29 272.75,27.75 TP18.TP | v186.75,25 186.75,26 182.19,30.55 IC4.22
N$57
  Bottom 0.5: Q3.1 Q2.2 105,50.85 R2.2
N$58
  Bottom 0.5: Q1.2 111,50.85 R1.2
N$59  (via drill 0.7)
  Top 0.5: v100,55.25 104.5,55.25 v109,50.75 v115,50.75
  Bottom 0.5: v100,55.25 Q3.3 98.6,53.1 97.5,52 97.5,47.5 R8.2 | Q2.1 107.1,50.75 v109,50.75 | Q1.1 113.1,50.75 v115,50.75
N$60
  Bottom 0.5: Q4.1 19.65,7.9 R10.1
N$61
  Bottom 0.5: R11.2 13.6,10.1 Q4.3 16.5,12 B2.2
N$62
  Bottom 0.5: LED7.K LED6.A
N$63
  Bottom 0.5: G1.P 11.25,22.75 C7.1 12.55,30.55 IC1.19
N$64
  Bottom 0.5: Q2.3 Q1.3 119.48,53.1 LED5.K
N$65
  Bottom 0.5: LED5.A 122.92,51.67 120.38,49.13 LED6.K
N$66
  Bottom 0.5: IC7.26 180.95,56.8 R4.1
N$67
  Bottom 0.5: IC7.25 182.7,57.8 R3.1
N$68
  Bottom 0.5: IC5.8 71.09,36.91 67,41 67,54 61.5,59.5 41.25,59.5 37.25,63.5 37.25,66.25 38.25,67.25 43.75,67.25 44.1,66.9 HN1.8
N$69
  Bottom 0.5: C5.1 20,31.5 19.68,31.82 IC1.18 14.18,31.82 11.63,34.37 IC1.5
N$90
  Bottom 1.5: D1.A 331.4,21 X1.CENTER
OE  (via drill 0.7)
  Top 0.5: v37,43.25 37.25,43.25 41.65,38.85 80.4,38.85 TP11.TP 117.5,31.25 119,29.75 124.25,29.75 125.75,31.25 v184,31.25 v291,31.25
  Bottom 0.5: TP11.TP 87.42,31.82 IC5.21 | v184,31.25 183.43,31.82 IC4.21 | IC3.21 290.43,31.82 v291,31.25 | IC2.12 39.78,40.72 37.25,43.25 v37,43.25
OUT_NTC  (via drill 0.7)
  Top 0.5: v54.75,26.25 54.75,19.5 61.25,13 303.25,13 323.5,33.25 X2.1
  Bottom 0.5: IC2.26 52.47,29.29 53,28.75 53,27.9 54.65,26.25 v54.75,26.25 55,26 R15.1
PGC
  Bottom 0.5: IC2.27 49.48,28.02 48.5,29 48.5,43.42 X5.5 51.08,51.67 50.5,52.25 48.25,52.25 47.81,51.81 X6.5
PGD
  Bottom 0.5: IC2.28 49.26,26.75 47.5,28.5 47.5,44.96 X5.4 46.54,48 X6.4
RIGHT
  Bottom 0.5: JOY1.5 7.55,55.45 15.5,47.5 18.5,47.5 23.75,42.25 23.75,36.25 30.71,29.29 IC2.3
RTC_CLK  (via drill 0.7)
  Top 0.5: TP1.TP 29.25,37 v5.25,37
  Bottom 0.5: IC2.10 34.08,38.17 TP1.TP | v5.25,37 5.34,36.91 IC1.7
SCK  (via drill 0.7)
  Top 0.5: v37,45.5 36.5,45.5 35.25,44.25 35.25,40.25 38.65,36.85 65.15,36.85 67.25,34.75 67.25,29.25 68.25,28.25 TP12.TP 72.75,28.25 73.25,27.75 149,27.75 149.75,27 v161.75,27 v269.5,27
  Bottom 0.5: IC5.3 72.31,30.55 TP12.TP | IC3.3 273.06,30.55 v269.5,27 | v161.75,27 165.31,30.55 IC4.3 | IC2.14 39.49,43.26 37.25,45.5 v37,45.5
SCL  (via drill 0.7)
  Top 0.5: v5.25,29.25 29.5,29.25 36,22.75 39.75,22.75 52.25,35.25 v54.75,35.25 56.25,35.25 59.5,32 59.5,20.75 60.75,19.5 302.5,19.5 324,41 324,53.25 TP7.TP X4.3
  Bottom 0.5: IC1.1 5.29,29.29 v5.25,29.25 | IC2.21 54.37,35.63 v54.75,35.25 56,35.25 R12.1
SDA  (via drill 0.7)
  Top 0.5: v5.25,33 5,33 3.25,31.25 3.25,28.2 3.95,27.5 29.75,27.5 35.5,21.75 40.25,21.75 49.25,30.75 v54.75,30.75 56.25,30.75 57.5,29.5 57.5,19.75 61.25,16 300.5,16 326,41.5 TP6.TP X4.1
  Bottom 0.5: IC1.4 5.34,33.09 arc90 v5.25,33 | R13.1 55.5,31.5 v54.75,30.75 54.25,31.25 54,31.25 53.42,31.82 IC2.24
SDI  (via drill 0.7)
  Top 0.5: v291.75,28 293,28 294,29 294,32.5 292,34.5 88.25,34.5 80.5,42.25 TP13.TP
  Bottom 0.5: IC3.22 289.19,30.55 v291.75,28 | IC2.15 52.51,43.26 53.25,44 61,44 TP13.TP
SDO  (via drill 0.7)
  Top 0.5: TP14.TP 66,25.5 62.75,28.75 v62.75,35
  Bottom 0.5: v62.75,35 62.75,39.5 59.25,43 53.75,43 52.73,41.98 IC2.16 | IC5.2 72.53,29.29 72,28.75 72,27.5 TP14.TP
UP
  Bottom 0.5: JOY1.1 15.75,51.75 24.75,42.75 24.75,36.75 30.95,30.55 IC2.4
VDD
  Top 1.5: 49.18,11 40.75,11 39.02,9.27 HN1.1 | 204.28,11 194.12,11 | HN2.5 97.5,4.97 97.5,11 | 87.32,11 HN2.1 | 97.5,11 87.32,11 | 145.82,11 HN3.1 | 145.82,11 97.5,11 | 155.98,11 HN3.5 | 155.98,11 145.82,11 | 204.28,11 HN4.5 | 252.62,11 262.78,11 | 194.12,11 HN4.1 | 194.12,11 155.98,11 | HN5.1 252.62,11 | 252.62,11 204.28,11 | 262.78,11 HN5.5 | 262.78,11 300.92,11 | 300.92,11 HN6.1 | 49.18,11 HN1.5 | 87.32,11 49.18,11 | 300.92,11 310.25,11 311.08,10.17 HN6.5
  Bottom 0.5: LED4.A 227.77,20.02 222.25,14.5 210,14.5 204.28,8.78 HN4.5 | HN2.5 97.48,8.73 103.25,14.5 115.5,14.5 120.97,19.97 120.97,21.25 | 120.97,21.25 LED2.A | B2.1 R11.1 10.5,7.75 13.25,5 TP3.TP | 120.97,21.25 120.72,21 117.25,21 113,25.25 C10.1 LED7.A
  Bottom 1: TP3.TP 30.05,4.95 HN1.1 39.02,8.27 39.31,8.56 IC6.1 39.41,13 C11.1
  Bottom 1.3: D1.C 321,20.8 321,16 322,15 C8.1 322,9 317.95,4.95 HN6.5

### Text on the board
bPlace: Kello v4.1 | 2018
tNames: IN | OUT | 9-12 VDC
bNames: INPUT | +3V3 | 9-12 VDC | GND | 800 mA | IN | OUT
_tsilk: HN1 | HN2 | HN4 | HN5 | HN3 | HN6 | B1 | JOY1 | LED5 | X4 | LED1 | LED3 | IN | X3 | LED6 | G1 | OUT | X2 | LED7 | 9-12 VDC | LED2 | LED4 | B2 | X1
_bsilk: C9 | C13 | Kello v4.1 | R5 | TP16 | INPUT | R3 | TP7 | +3V3 | IR | R4 | SCL | Q3 | Q2 | Q1 | IC7 | 9-12 VDC | TP6 | GND | SDA | X6 | R8 | R2 | R1 | 2018 | PICkit 2/3 | TP5 | TP4 | X5 | GPS_RX | GPS_TX | TP13 | 800 mA | IC5 | TP9 | IC4 | IC3 | IC1 | TP1 | IN | SDI | IRED | RTC_CLK | C4 | R12 | TP11 | C10 | OUT | TP10 | R13 | LE | TP12 | R14 | OE | SCK | TP18 | TP17 | R15 | TP14 | C3 | R9 | C2 | R7 | C1 | R6 | C7 | C6 | C5 | IC2 | TP2 | SDO | IC4SDO | D1 | IC5SDO | +3v3 | TP15 | IC6 | TP8 | BRI | C12 | C11 | C8 | BUZ | R11 | Q4 | R10 | TP3 | VDD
